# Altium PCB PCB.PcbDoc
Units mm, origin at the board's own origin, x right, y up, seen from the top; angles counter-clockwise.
Board outline 41 x 25.36 mm, 2 copper layers (TOP, BOTTOM), stack 1.586 mm thick; 59 components, 45 nets, 178 pads, 69 vias.
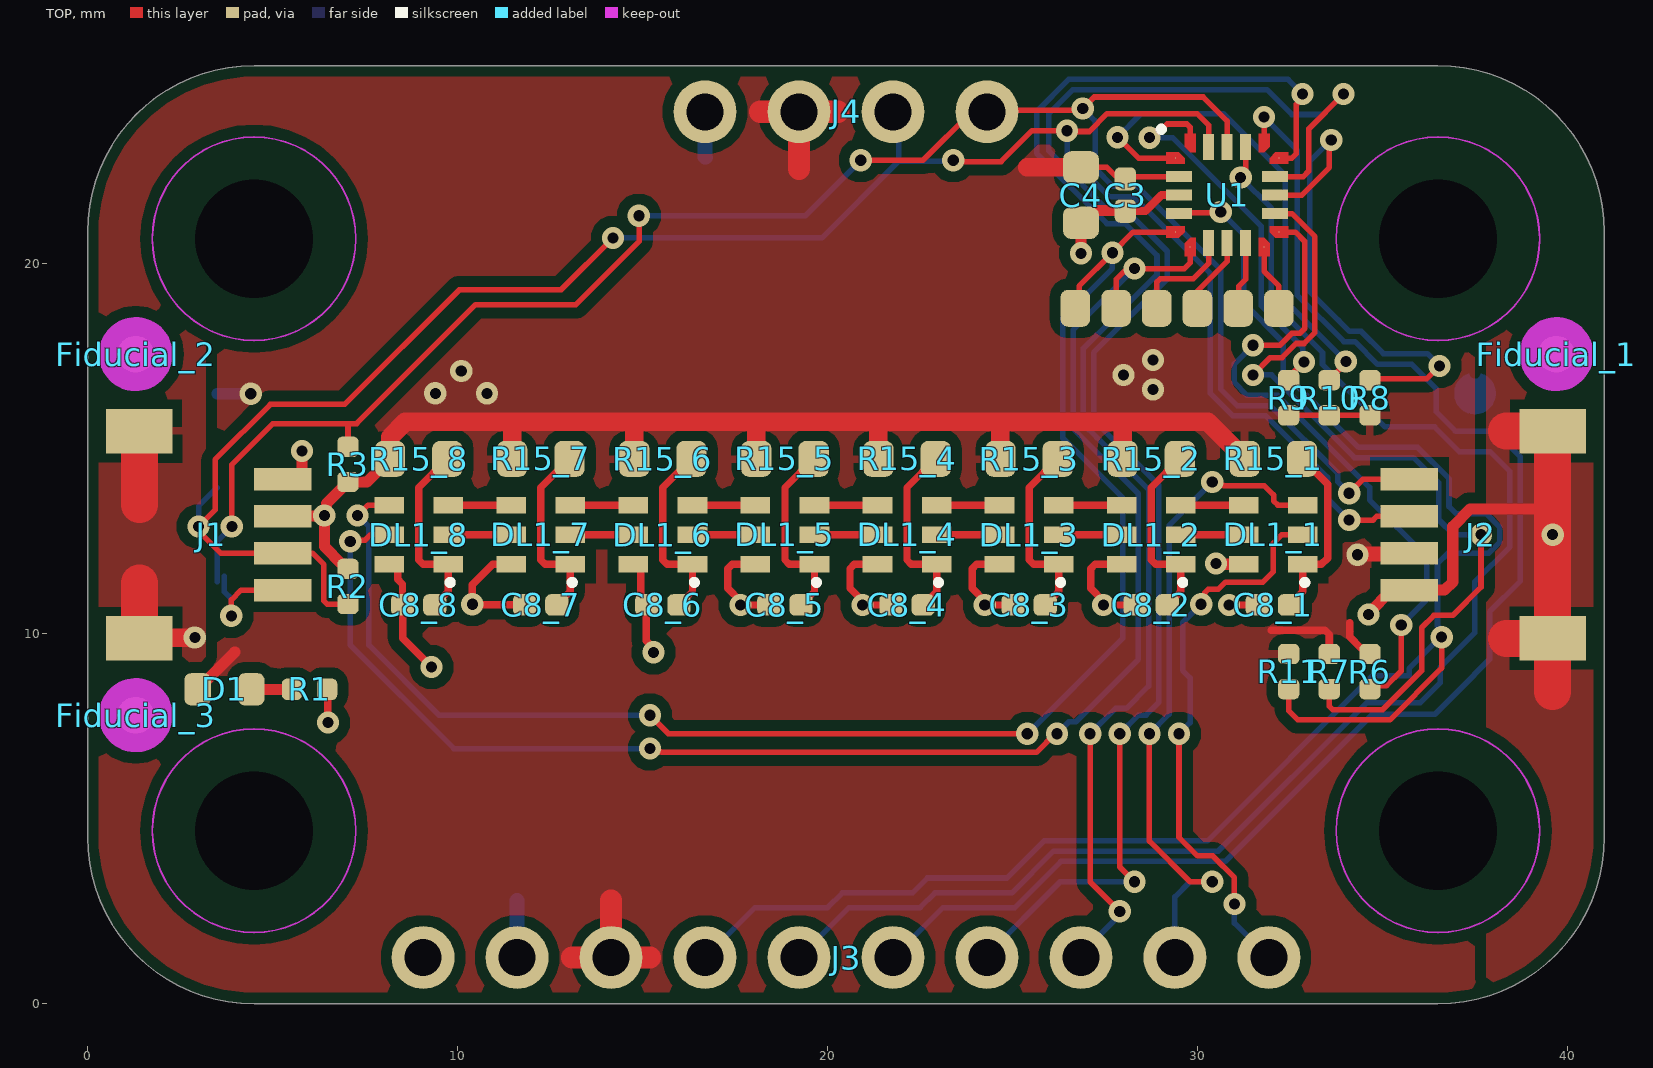
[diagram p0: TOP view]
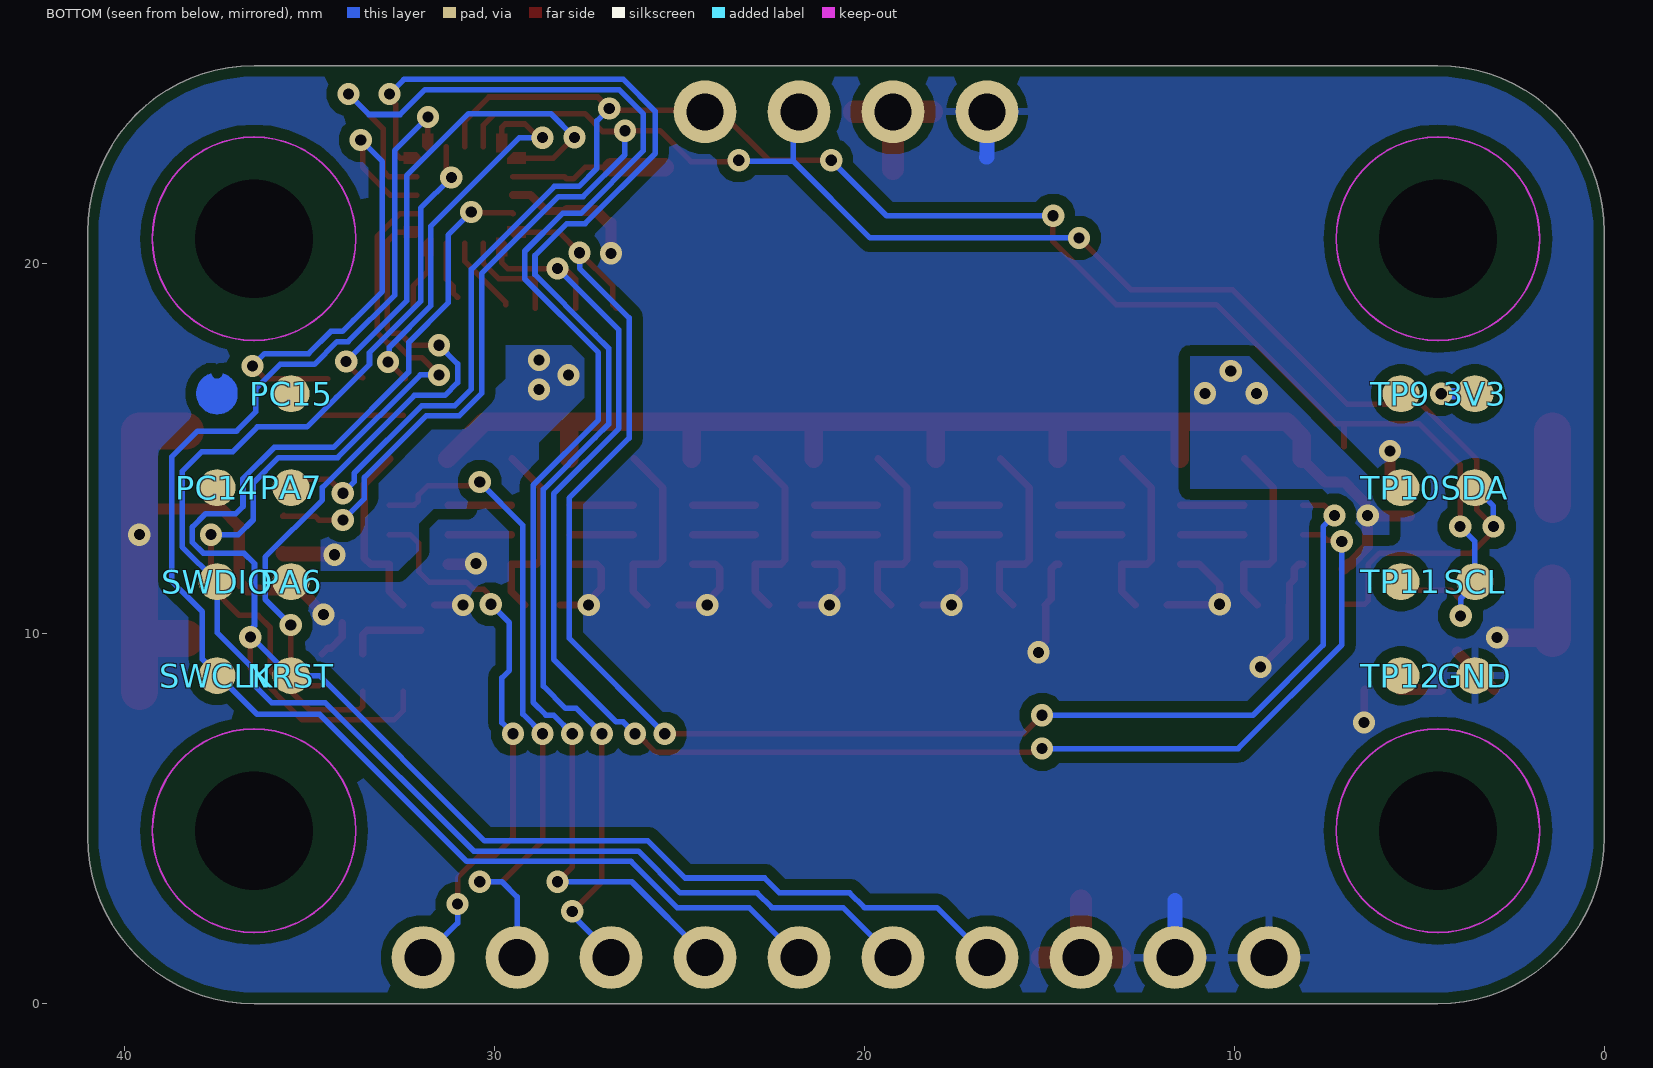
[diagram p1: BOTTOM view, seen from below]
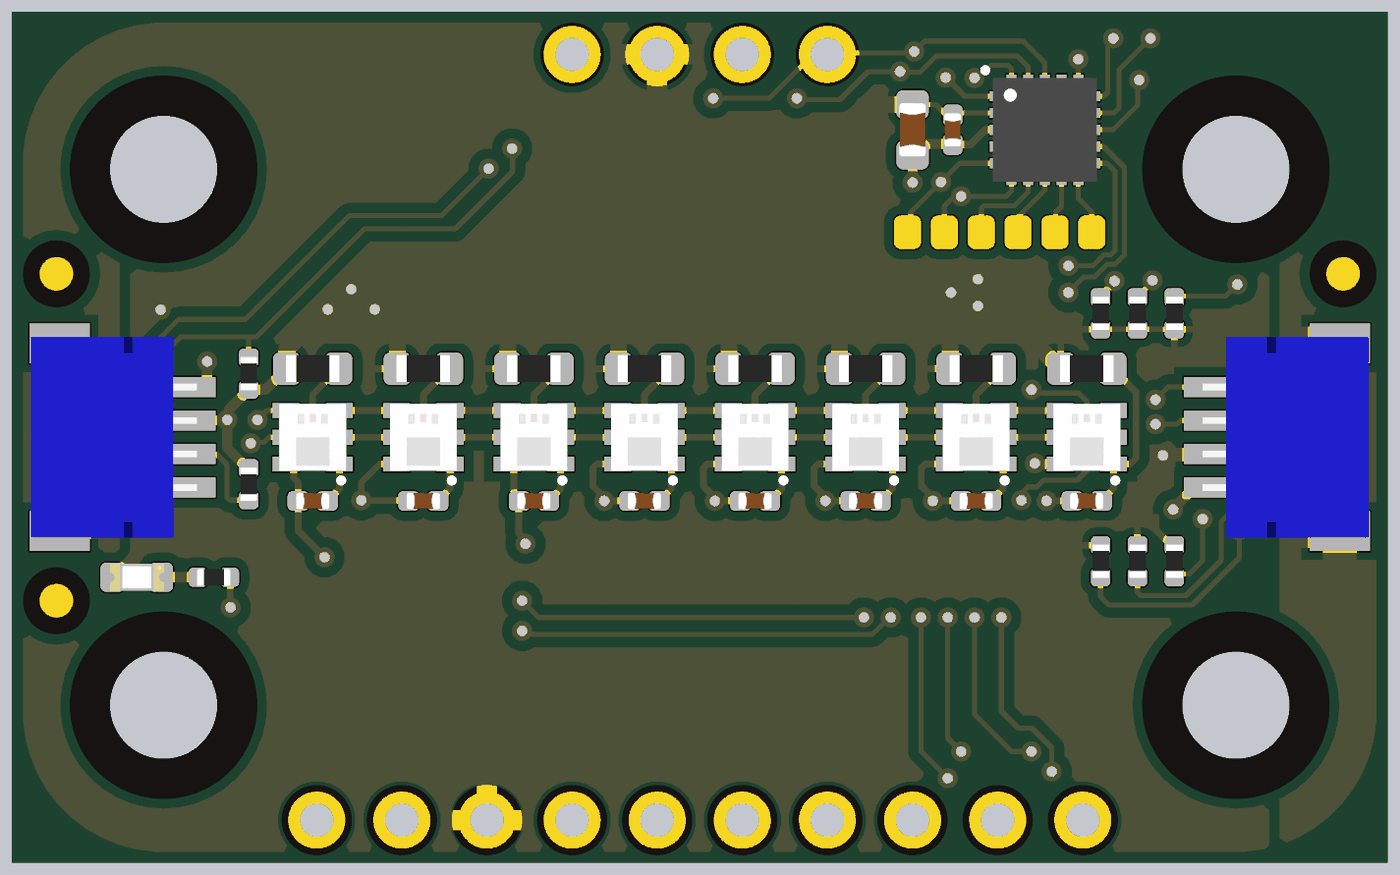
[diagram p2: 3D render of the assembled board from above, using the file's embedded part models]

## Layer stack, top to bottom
Top Solder: solder mask 0.01, Solder Resist, Dk 3.5
TOP: signal copper 0.018
Dielectric: core 1.55, FR-4, Dk 4.8
BOTTOM: signal copper 0.018
Bottom Solder: solder mask 0.01, Solder Resist, Dk 3.5

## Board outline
0,4.5 ccw(c4.5,4.5) 4.5,0 36.5,0 ccw(c36.5,4.5) 41,4.5 41,20.86 ccw(c36.5,20.86) 36.5,25.36 4.5,25.36 ccw(c4.5,20.86) 0,20.86

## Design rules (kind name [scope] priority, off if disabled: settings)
BoardOutlineClearance Mousebites [(ObjectKind = 'Pad') And (Name = 'Free-MOUSEBITE')] p1: gap=0 ignorepadtopadclearanceinfootprint=FALSE
BoardOutlineClearance Silks [(OnLayer('Top Overlay') OR OnLayer('Bottom Overlay'))] p2: gap=0 ignorepadtopadclearanceinfootprint=FALSE
BoardOutlineClearance [All] p3: gap=0.3 ignorepadtopadclearanceinfootprint=FALSE
Clearance COPPER_0.3mm [All] p1: gap=0.127 ignorepadtopadclearanceinfootprint=FALSE except(0.3: Arc-Fill Arc-Poly Arc-Region Track-Fill Track-Poly Track-Region SMDPad-Fill SMDPad-Poly SMDPad-Region THPad-Fill THPad-Poly THPad-Region Via-Fill Via-Poly Via-Region Fill-Fill Fill-Poly Fill-Region Poly-Poly Poly-Region Region-Region)
Clearance "Generic clearance 0.15mm" [All] p2: gap=0.15 ignorepadtopadclearanceinfootprint=TRUE
ComponentClearance [All] p1: gap=0.2 collisioncheckmode=3 verticalgap=0 showdistances=TRUE
DiffPairsRouting USB [InDifferentialPairClass('USB')] p1: maxlimit=0.15 minlimit=0.15 mostfreqgap=0.15 toplayer_minwidth=0.15 toplayer_maxwidth=0.21 toplayer_prefwidth=0.2 bottomlayer_minwidth=0.15 bottomlayer_maxwidth=0.21 bottomlayer_prefwidth=0.2 impedanceprofiledriven=TRUE impedanceprofileid={E6B00C31-4C8E-439C-824F-D2B2CDC26F9C} impedanceprofilevalue=90.000000 maxuncoupledlength=12.7
Height [All] p1: minheight=0 maxheight=30 prefheight=12.7
HoleSize [All] p1: absolutevalues=TRUE maxlimit=30 minlimit=0.3 maxpercent=80.000 minpercent=20.000
HoleToHoleClearance [All] p1: gap=0.25 allowstackedmicrovias=FALSE
MinimumAnnularRing [All] p1: minimumring=0.15
NetAntennae NetAntennae_2 [(ObjectKind = 'Track') And (Layer = 'TOP') And (Net = 'BOOST_INPUT') And (PropagationDelay = '4.136ps')] p1: netantennaetolerance=5
NetAntennae NetAntennae_1 [(ObjectKind = 'Track') And (Layer = 'TOP') And (Net = '+5V') And (PropagationDelay = '4.136ps')] p2: netantennaetolerance=5
NetAntennae [All] p3: netantennaetolerance=0
PlaneConnect [All] p1: pad.planeconnectstyle=Relief pad.reliefexpansion=0.508 pad.reliefentries=4 pad.reliefconductorwidth=0.254 pad.reliefairgap=0.254 via.planeconnectstyle=Direct via.reliefexpansion=0.508 via.reliefentries=4 via.reliefconductorwidth=0.254 via.reliefairgap=0.254
PolygonConnect [All] p1: thpad.connectstyle=Relief thpad.reliefconductorwidth=0.2 thpad.reliefentries=4 thpad.polygonreliefangle="90 Angle" thpad.airgapwidth=0.254 smdpad.connectstyle=Relief smdpad.reliefconductorwidth=0.2 smdpad.reliefentries=4 smdpad.polygonreliefangle="90 Angle" smdpad.airgapwidth=0.254 via.connectstyle=Direct via.reliefconductorwidth=0.254 via.reliefentries=4 via.polygonreliefangle="90 Angle" via.airgapwidth=0.254
RoomDefinition U_RGBLED2 [InComponentClass('U_RGBLED2')] p1: confinementstyle=ConfineIn formatcopy=TRUE lockcomponents=FALSE outline 30.325,14.055 30.325,11.04 29.875,11.04 29.875,10.115 27.625,10.115 27.625,11.04 27.175,11.04 27.175,14.055 27.19,14.055 27.19,15.59 30.31,15.59 30.31,14.055
RoomDefinition U_RGBLED3 [InComponentClass('U_RGBLED3')] p2: confinementstyle=ConfineIn formatcopy=TRUE lockcomponents=FALSE outline 27.025,14.055 27.025,11.04 26.575,11.04 26.575,10.115 24.325,10.115 24.325,11.04 23.875,11.04 23.875,14.055 23.89,14.055 23.89,15.59 27.01,15.59 27.01,14.055
RoomDefinition U_RGBLED1 [InComponentClass('U_RGBLED1')] p3: confinementstyle=ConfineIn formatcopy=TRUE lockcomponents=FALSE outline 33.525,14.055 33.525,11.04 33.075,11.04 33.075,10.115 30.825,10.115 30.825,11.04 30.375,11.04 30.375,14.055 30.39,14.055 30.39,15.59 33.51,15.59 33.51,14.055
RoomDefinition U_RGBLED4 [InComponentClass('U_RGBLED4')] p4: confinementstyle=ConfineIn formatcopy=TRUE lockcomponents=FALSE outline 23.725,14.055 23.725,11.04 23.275,11.04 23.275,10.115 21.025,10.115 21.025,11.04 20.575,11.04 20.575,14.055 20.59,14.055 20.59,15.59 23.71,15.59 23.71,14.055
RoomDefinition U_RGBLED5 [InComponentClass('U_RGBLED5')] p5: confinementstyle=ConfineIn formatcopy=TRUE lockcomponents=FALSE outline 20.525,14.055 20.525,11.04 20.075,11.04 20.075,10.115 17.825,10.115 17.825,11.04 17.375,11.04 17.375,14.055 17.39,14.055 17.39,15.59 20.51,15.59 20.51,14.055
RoomDefinition U_RGBLED6 [InComponentClass('U_RGBLED6')] p6: confinementstyle=ConfineIn formatcopy=TRUE lockcomponents=FALSE outline 17.125,14.055 17.125,11.04 16.675,11.04 16.675,10.115 14.425,10.115 14.425,11.04 13.975,11.04 13.975,14.055 13.99,14.055 13.99,15.59 17.11,15.59 17.11,14.055
RoomDefinition U_RGBLED7 [InComponentClass('U_RGBLED7')] p7: confinementstyle=ConfineIn formatcopy=TRUE lockcomponents=FALSE outline 27.175,11.305 27.175,14.32 27.625,14.32 27.625,15.245 29.875,15.245 29.875,14.32 30.325,14.32 30.325,11.305 30.31,11.305 30.31,9.77 27.19,9.77 27.19,11.305
RoomDefinition U_RGBLED8 [InComponentClass('U_RGBLED8')] p8: confinementstyle=ConfineIn formatcopy=TRUE lockcomponents=FALSE outline 10.525,14.055 10.525,11.04 10.075,11.04 10.075,10.115 7.825,10.115 7.825,11.04 7.375,11.04 7.375,14.055 7.39,14.055 7.39,15.59 10.51,15.59 10.51,14.055
RoomDefinition TOP [InComponentClass('TOP')] p9: confinementstyle=ConfineIn formatcopy=TRUE lockcomponents=FALSE outline 42.7,5.4 51.6,5.4 51.6,19.2 42.7,19.2
RoutingVias StandardVias [All] p1: holewidth=0.3 width=0.6 viastyle="Through Hole" minholewidth=0.3 minwidth=0.6 maxholewidth=0.3 maxwidth=0.6
SMDToCorner [All] p1: distance=39370
ShortCircuit ShortCircuit_2 [(ObjectKind = 'Pad') And (Component = 'SJ1') And (Name = 'SJ1-1')] p1: allowed=TRUE
ShortCircuit ShortCircuit_1 [(ObjectKind = 'Pad') And (Component = 'SJ2') And (Name = 'SJ2-2')] p2: allowed=TRUE
ShortCircuit [All] p3: allowed=FALSE
SilkToSilkClearance [All] p1: silktosilkclearance=0.2
SilkToSolderMaskClearance [IsPad] p1: minsilkscreentomaskgap=0.15 clearancetoexposedcopper=TRUE
SolderMaskExpansion VIAtented [IsVia] p1: expansion=0.102 istentingtop=TRUE
SolderMaskExpansion [All] p2: expansion=0.05 istentingtop=FALSE
UnConnectedPin [All] p1:
UnRoutedNet [not WithinRoom('K36')] p1: checkbadconnections=TRUE
ViasUnderSMD [All] p1: allowed=FALSE
Width StandardTraces [All] p1: maxlimit=5 minlimit=0.15 preferedwidth=0.15 minimp=50.000000 maximp=50.000000 favimp=50.000000
19 further rules are at their usual default settings.

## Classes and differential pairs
channel class RGBLED: U_RGBLED1 U_RGBLED2 U_RGBLED3 U_RGBLED4 U_RGBLED5 U_RGBLED6 U_RGBLED7 U_RGBLED8
component class U_RGBLED8: C8_8 DL1_8 R15_8
component class U_RGBLED7: C8_7 DL1_7 R15_7
component class U_RGBLED6: C8_6 DL1_6 R15_6
component class U_RGBLED5: C8_5 DL1_5 R15_5
component class U_RGBLED4: C8_4 DL1_4 R15_4
component class U_RGBLED3: C8_3 DL1_3 R15_3
component class U_RGBLED2: C8_2 DL1_2 R15_2
component class U_RGBLED1: C8_1 DL1_1 R15_1
component class TOP: 3V3 D1 Fiducial_1 Fiducial_2 Fiducial_3 GND J1 J2 J3 J4 NRST PA6 PA7 PC14 PC15 R1 SCL SDA SWCLK SWDIO TP9 TP10 TP11 TP12
component class U_MICROCONTROLLER: C3 C4 R2 R3 R6 R7 R8 R9 R10 R11 U1

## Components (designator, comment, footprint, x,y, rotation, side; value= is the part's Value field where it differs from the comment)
3V3 "Test point 1.00mm" TP-1.00MM 3.5,16.49 r90 bottom
C3 "0402B104K160CT" CAP-0402 28.05,21.86 r270 top value=100nF
C4 "GRM188R61C475KAAJD" CAP-0603 26.85,21.86 r90 top value=4.7µF
C8_1 "0402B104K160CT" CAP-0402 32.05,10.78 r180 top value=100nF (schematic designator C8)
C8_2 "0402B104K160CT" CAP-0402 28.75,10.78 r180 top value=100nF (schematic designator C8)
C8_3 "0402B104K160CT" CAP-0402 25.45,10.78 r180 top value=100nF (schematic designator C8)
C8_4 "0402B104K160CT" CAP-0402 22.15,10.78 r180 top value=100nF (schematic designator C8)
C8_5 "0402B104K160CT" CAP-0402 18.85,10.78 r180 top value=100nF (schematic designator C8)
C8_6 "0402B104K160CT" CAP-0402 15.55,10.78 r180 top value=100nF (schematic designator C8)
C8_7 "0402B104K160CT" CAP-0402 12.25,10.78 r180 top value=100nF (schematic designator C8)
C8_8 "0402B104K160CT" CAP-0402 8.95,10.78 r180 top value=100nF (schematic designator C8)
D1 "HSMG-C190" LEDC1608X80N-AK 3.7,8.5 r180 top
DL1_1 "LC8822-2020" APA102-2020 32.05,12.68 r180 top (schematic designator DL1)
DL1_2 "LC8822-2020" APA102-2020 28.75,12.68 r180 top (schematic designator DL1)
DL1_3 "LC8822-2020" APA102-2020 25.45,12.68 r180 top (schematic designator DL1)
DL1_4 "LC8822-2020" APA102-2020 22.15,12.68 r180 top (schematic designator DL1)
DL1_5 "LC8822-2020" APA102-2020 18.85,12.68 r180 top (schematic designator DL1)
DL1_6 "LC8822-2020" APA102-2020 15.55,12.68 r180 top (schematic designator DL1)
DL1_7 "LC8822-2020" APA102-2020 12.25,12.68 r180 top (schematic designator DL1)
DL1_8 "LC8822-2020" APA102-2020 8.95,12.68 r180 top (schematic designator DL1)
Fiducial_1 "Fiducial mark 1mm" "Fiducial mark 1mm-Footprint-1" 39.7,17.56 r270 top
Fiducial_2 "Fiducial mark 1mm" "Fiducial mark 1mm-Footprint-1" 1.3,17.56 r270 top
Fiducial_3 "Fiducial mark 1mm" "Fiducial mark 1mm-Footprint-1" 1.3,7.8 r270 top
GND "Test point 1.00mm" TP-1.00MM 3.5,8.87 r90 bottom
J1 "SM04B-SRSS-TB(LF)(SN)" SM04B-SRSS-TB(LF)(SN)-Footprint-1 3.337,12.68 r90 top locked
J2 "SM04B-SRSS-TB(LF)(SN)" SM04B-SRSS-TB(LF)(SN)-Footprint-1 37.663,12.68 r270 top locked
J3 "HEADER TH 2.54mm VERT. 1x010POS" "PIN HEADER 2.54mm VERT. 1x10POS" 20.5,1.25 r0 top
J4 "HEADER TH 2.54mm VERT. 1x004POS" "PIN HEADER 2.54mm VERT. 1x4POS-Footprint-1" 20.5,24.11 r0 top
NRST "Test point 1.00mm" TP-1.00MM 35.5,8.87 r180 bottom
PA6 "Test point 1.00mm" TP-1.00MM 35.5,11.41 r180 bottom
PA7 "Test point 1.00mm" TP-1.00MM 35.5,13.95 r180 bottom
PC14 "Test point 1.00mm" TP-1.00MM 37.5,13.95 r180 bottom
PC15 "Test point 1.00mm" TP-1.00MM 35.5,16.49 r180 bottom
R1 "CRCW04021K00FKEDC" RES-0402 6,8.5 r180 top value=1k
R2 "RC0402FR-074K7L" RES-0402 7.039,11.28 r90 top value=4.7k
R3 "RC0402FR-074K7L" RES-0402 7.039,14.58 r270 top value=4.7k
R6 "RC0402FR-074K7L" RES-0402 34.663,8.98 r270 top value=4.7k
R7 "RC0402FR-074K7L" RES-0402 33.563,8.98 r270 top value=4.7k
R8 "RC0402FR-074K7L" RES-0402 34.663,16.38 r90 top value=4.7k
R9 "RC0402FR-074K7L" RES-0402 32.463,16.38 r90 top value=4.7k
R10 "RC0402FR-074K7L" RES-0402 33.563,16.38 r90 top value=4.7k
R11 "RC0402FR-074K7L" RES-0402 32.463,8.98 r270 top value=4.7k
R15_1 "CRCW060310R0FKEAC" RES-0603 32.05,14.73 r180 top value=10 (schematic designator R15)
R15_2 "CRCW060310R0FKEAC" RES-0603 28.75,14.73 r180 top value=10 (schematic designator R15)
R15_3 "CRCW060310R0FKEAC" RES-0603 25.45,14.73 r180 top value=10 (schematic designator R15)
R15_4 "CRCW060310R0FKEAC" RES-0603 22.15,14.73 r180 top value=10 (schematic designator R15)
R15_5 "CRCW060310R0FKEAC" RES-0603 18.85,14.73 r180 top value=10 (schematic designator R15)
R15_6 "CRCW060310R0FKEAC" RES-0603 15.55,14.73 r180 top value=10 (schematic designator R15)
R15_7 "CRCW060310R0FKEAC" RES-0603 12.25,14.73 r180 top value=10 (schematic designator R15)
R15_8 "CRCW060310R0FKEAC" RES-0603 8.95,14.73 r180 top value=10 (schematic designator R15)
SCL "Test point 1.00mm" TP-1.00MM 3.5,11.41 r90 bottom
SDA "Test point 1.00mm" TP-1.00MM 3.5,13.95 r90 bottom
SWCLK "Test point 1.00mm" TP-1.00MM 37.5,8.87 r180 bottom
SWDIO "Test point 1.00mm" TP-1.00MM 37.5,11.41 r180 bottom
TP9 "Test point 1.00mm" TP-1.00MM 5.5,16.49 r0 bottom
TP10 "Test point 1.00mm" TP-1.00MM 5.5,13.95 r0 bottom
TP11 "Test point 1.00mm" TP-1.00MM 5.5,11.41 r0 bottom
TP12 "Test point 1.00mm" TP-1.00MM 5.5,8.87 r0 bottom
U1 "STM32C011F4U6TR" UFQFPN20 30.8,21.86 r0 top

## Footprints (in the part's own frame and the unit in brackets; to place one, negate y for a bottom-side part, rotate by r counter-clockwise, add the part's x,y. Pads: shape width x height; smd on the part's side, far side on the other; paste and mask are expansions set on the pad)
APA102-2020 [mm]
  rect 0.8x0.45 smd mask+0.05: 1(-0.8,0.8) 2(-0.8,0) 3(-0.8,-0.8) 4(0.8,0.8) 5(0.8,0) 6(0.8,-0.8)
  silkscreen extent -0.9,1.24 -0.8,1.34, body extent -1,-1 1,1, height 0.92
CAP-0402 [mm] "Chip Capacitor, 2-Leads, Body  0402 (in) 1005 (mm), IPC Medium Density"
  rrect52% 0.63x0.58 smd mask+0.05: 1(-0.435,0) 2(0.435,0)
  body extent -0.5,-0.25 0.5,0.25, height 0.5
CAP-0603 [mm] "Chip Capacitor, Body 0603 imperial,1.6x0.8mm, IPC High Density"
  rrect51% 0.87x0.97 smd mask+0.05: 1(-0.75,0) 2(0.75,0)
  body extent -0.8,-0.4 0.8,0.4, height 0.8
"Fiducial mark 1mm-Footprint-1" [mm]
  round 1 smd paste-10 mask+0.5: 1(0,0)
  TOP keep-out circle w1: c0,0 r0.5
LEDC1608X80N-AK [mm]
  rrect50% 0.72x0.87 smd: A(0.725,0) C(-0.725,0)
  body extent -0.8,-0.4 0.8,0.4, height 0.79
"PIN HEADER 2.54mm VERT. 1x4POS-Footprint-1" [mm]
  round 1.7 hole 1 mask+0.1: 1(-3.81,0) 2(-1.27,0) 3(1.27,0) 4(3.81,0)
"PIN HEADER 2.54mm VERT. 1x10POS" [mm]
  round 1.7 hole 1 mask+0.2: 1(-11.43,0) 2(-8.89,0) 3(-6.35,0) 4(-3.81,0) 5(-1.27,0) 6(1.27,0) 7(3.81,0) 8(6.35,0) 9(8.89,0) 10(11.43,0)
RES-0402 [mm] "Chip Resistor, 2-Leads, Body  0402 (in) 1005 (mm), IPC Medium Density"
  rrect51% 0.55x0.58 smd mask+0.05: 1(-0.475,0) 2(0.475,0)
  body extent -0.5,-0.25 0.5,0.25, height 0.34
RES-0603 [mm] "Chip Resistor - Body 0603 imperial,1.6x0.8mm, IPC High Density"
  rrect51% 0.82x0.97 smd mask+0.05: 1(-0.775,0) 2(0.775,0)
  body extent -0.8,-0.4 0.8,0.4, height 0.43
SM04B-SRSS-TB(LF)(SN)-Footprint-1 [mm]
  rect 0.6x1.55 smd mask+0.05: 1(1.5,-1.937) 2(0.5,-1.937) 3(-0.5,-1.937) 4(-1.5,-1.937)
  rect 1.2x1.8 smd mask+0.05: FIX(-2.8,1.938) FIX(2.8,1.938)
  body extent -3,-2.16 3,2.8, height 2.98
TP-1.00MM [mm]
  rrect100% 1x1 smd paste-2.54: X(0,0)
UFQFPN20 [mm] "QFN, 20-Leads, Body 3.00x3.00mm, Pitch 0.50mm, IPC Medium Density"
  round 0.025 smd mask+0.05: 1(-1.4,1) 5(-1.4,-1) 6(-1,-1.4) 10(1,-1.4) 11(1.4,-1) 15(1.4,1) 16(1,1.4) 20(-1,1.4)
  rect 0.7x0.3 smd mask+0.05: 2(-1.3,0.5) 3(-1.3,0) 4(-1.3,-0.5) 12(1.3,-0.5) 13(1.3,0) 14(1.3,0.5)
  rect 0.3x0.7 smd mask+0.05: 7(-0.5,-1.3) 8(0,-1.3) 9(0.5,-1.3) 17(0.5,1.3) 18(0,1.3) 19(-0.5,1.3)
  TOP region: -1.3,-1.15 -1.15,-1 -1.15,-0.85 -1.65,-0.85 -1.65,-1.15
  TOP region: -0.85,-1.65 -1.15,-1.65 -1.15,-1.3 -1,-1.15 -0.85,-1.15
  TOP region: 1.15,-1.65 0.85,-1.65 0.85,-1.15 1,-1.15 1.15,-1.3
  TOP region: 1.65,1.15 1.65,0.85 1.15,0.85 1.15,1 1.3,1.15
  TOP region: 1,1.15 0.85,1.15 0.85,1.65 1.15,1.65 1.15,1.3
  TOP region: -1.15,1 -1.15,0.85 -1.65,0.85 -1.65,1.15 -1.3,1.15
  TOP region: -1.15,1.3 -1,1.15 -0.85,1.15 -0.85,1.65 -1.15,1.65
  TOP region: 1.65,-0.85 1.65,-1.15 1.3,-1.15 1.15,-1 1.15,-0.85
  silkscreen extent -1.8,1.75 -1.75,1.8, body extent -1.55,-1.55 1.55,1.55, height 0.6

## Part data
3V3 GND NRST PA6 PA7 PC14 PC15 SCL SDA SWCLK SWDIO TP9 TP10 TP11 TP12: library part UT0013-A.6, Manufacturer="This is not a component"
C3 C8_1 C8_2 C8_3 C8_4 C8_5 C8_6 C8_7 C8_8: library part C0012-A.15, "CAP CHIP 0402 100nF 10% 16V X7R", Case Code (Imperial)=0402, Dielectric=X7R, Manufacturer=Walsin, Tolerance=10%, Voltage=16V
C4: library part C0054-A.16, "CAP CHIP 0603 4.7uF 10% 16V X5R", Case Code (Imperial)=0603, Dielectric=X5R, Manufacturer=Murata, Manufacturer 3="Samsung Electro-Mechanics", Part number 2=GRM188R61C475KE11D, Part number 3=CL10A475KO8NNNC, Tolerance=10%, Voltage=16V
D1: library part L0009-A.5, "LED SMD 0603 GREEN/568 15mcd 120^", Manufacturer=Broadcom
DL1_1 DL1_2 DL1_3 DL1_4 DL1_5 DL1_6 DL1_7 DL1_8: library part L0003-A.11, "LED RGB DATA + CLOCK 2020 2x2x.0.7mm", Manufacturer="Shenzhen LED Color Opto Electronic CO.,LTD."
Fiducial_1 Fiducial_2 Fiducial_3: library part UT0023-A.7, "Fiducial mark 1mm clearance 2mm"
J1 J2: library part J0005-A.2, "CONN JST 4POS SIDE 1MM TIN QWIIC", Manufacturer=JST
J3: library part J0169-A.8
J4: library part J0162-A.5
R1: library part R0007-A.24, "RES CHIP 0402 1k 1% 1/16W", Case Code (Imperial)=0402, Manufacturer=Vishay, Power=62.5mW, Temperature Coefficient=100ppm, Tolerance=1%
R2 R3 R6 R7 R8 R9 R10 R11: library part R0013-A.24, "RES CHIP 0402 4k7 1% 1/16W", Case Code (Imperial)=0402, Manufacturer=YAGEO, Power=62.5mW, Temperature Coefficient=200ppm, Tolerance=1%
R15_1 R15_2 R15_3 R15_4 R15_5 R15_6 R15_7 R15_8: library part R0188-A.20, "RES CHIP 0603 10R 1% 1/10W", Case Code (Imperial)=0603, Manufacturer=Vishay, Power=100mW, Temperature Coefficient=100ppm, Tolerance=1%
U1: library part U0363-A.3, "IC Cortex M0, 32b MCU, 32KB Flash, 6KB RAM, VDD 2-3.6V, -40°C to 85°C, QFN20 3x3mm", Manufacturer="ST Microelectronics"

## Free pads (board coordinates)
  rrect50% 0.8x1 smd paste-2539.97: 3V8(28.9,18.8) 3V9(26.7,18.8) 3V9(27.8,18.8) 3V9(30,18.8) 3V10(31.1,18.8) 3V10(32.2,18.8)
  round 3 hole 3.2 unplated paste-2539.97 mask+1.3: MH(4.5,4.68) MH(4.5,20.68) MH(36.5,4.68) MH(36.5,20.68)

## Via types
v1: diameter 0.6, hole 0.3, TOP to BOTTOM, tented both sides, 69 vias

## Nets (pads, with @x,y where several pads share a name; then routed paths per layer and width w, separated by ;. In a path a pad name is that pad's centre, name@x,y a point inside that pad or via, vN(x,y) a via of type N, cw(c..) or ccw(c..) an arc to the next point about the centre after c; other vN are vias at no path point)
+3V3: 3V3.X C3.1 C4.2 D1.A J1.2 J2.2 J3.3 J4.2 R2.2 R3.2 R6.1 R7.1 R8.1 R9.1 R10.1 R11.1 R15_1.2 R15_2.2 R15_3.2 R15_4.2 R15_5.2 R15_6.2 R15_7.2 R15_8.2 U1.2 | length 56.7
  TOP w0.15: C4.2 27.55,22.61 27.865,22.295 C3.1 28.115,22.36 U1.2 ; R9.1 R10.1 R8.1
  TOP w0.2: 31.998,10.1 33.446,10.1 33.563,9.983 R7.1 ; 34.113,10.298 34.113,9.916 34.424,9.605 34.513,9.605 R6.1
  TOP w0.3: D1.A 3.98,9.505 ; J1.2 5.284,13.19 6.39,13.19 v1(6.4,13.2) ; R2.2 6.914,11.88 6.877,11.88 6.4,12.357 v1(6.4,13.2) ; R15_8.2 7.55,14.105 R3.2 7.024,14.105 6.899,13.98 6.899,13.965 6.457,13.523 6.457,13.257 v1(6.4,13.2)
  TOP w0.4: v1(34.324,12.138) 34.344,12.159 35.705,12.159 J2.2
  TOP w0.5: R15_8.2 8.175,15.315 8.59,15.73 30.275,15.73 R15_1.2 ; R15_7.2 11.475,15.73 ; R15_6.2 14.775,15.73 ; R15_5.2 18.075,15.73 ; R15_4.2 21.375,15.73 ; R15_3.2 24.675,15.73 ; 25.4,22.61 C4.2 ; R15_2.2 27.975,15.73
  TOP w0.6: 13.1,1.25 J3.3 ; 14.15,2.79 J3.3 ; 15.2,1.25 J3.3 ; 18.18,24.11 J4.2 ; 19.23,22.57 J4.2 ; 20.28,24.11 J4.2
  BOTTOM w0.15: J3.3 J3.3@14.37,1.25
  BOTTOM w0.3: 3V3.X v1(4.41,16.49)
  other v1: 9.4,16.5 10.8,16.5 28.8,16.6 28,17 10.1,17.1 28.8,17.4
CO_1: DL1_1.2 J3.10 | length 15.3
  TOP w0.15: v1(29.5,7.3) 29.5,4.5 30.002,3.998 30.412,3.998 31,3.41 v1(31,2.7) ; v1(30.1,10.8) 30.1,10.922 30.2,11.022 30.2,11.112 30.288,11.2 30.56,11.2 30.76,11.4 31.77,11.4 32.05,11.68 32.05,12.45 32.28,12.68 DL1_1.2
  BOTTOM w0.15: v1(29.5,7.3) 29.8,7.6 29.8,8.811 29.6,9.011 29.6,10.3 v1(30.1,10.8) ; v1(31,2.7) 31,2.18 J3.10
DO_1: DL1_1.3 J3.9 | length 18.2
  TOP w0.15: v1(28.7,7.3) 28.7,4.4 29.8,3.3 v1(30.4,3.3) ; v1(30.4,14.1) 30.486,14.014 30.699,14.014 30.713,14 31.809,14 32.057,13.752 32.057,13.595 32.172,13.48 DL1_1.3
  BOTTOM w0.15: v1(28.7,7.3) 29.231,7.831 29.231,12.931 v1(30.4,14.1) ; J3.9 29.39,2.89 29.8,3.3 v1(30.4,3.3)
GND: C3.2 C4.1 C8_1.2 C8_2.2 C8_3.2 C8_4.2 C8_5.2 C8_6.2 C8_7.2 C8_8.2 DL1_1.4 DL1_2.4 DL1_3.4 DL1_4.4 DL1_5.4 DL1_6.4 DL1_7.4 DL1_8.4 GND.X J1.1 J1.FIX J2.1 J2.FIX J3.1 J3.2 J4.1 R1.1 U1.3 | length 51.8
  TOP w0.2: R1.1 6.488,8.488 6.488,7.612 v1(6.5,7.6) ; DL1_8.4 8.258,11.88 8.383,11.755 8.383,11.472 8.513,11.342 C8_8.2@8.513,10.78 ; C8_8.2 8.515,9.885 v1(9.3,9.1) ; DL1_7.4 10.95,11.88 10.4,11.33 v1(10.4,10.8) 10.41,10.79 11.805,10.79 C8_7.2 ; DL1_6.4 14.827,11.88 14.952,11.755 14.952,10.943 C8_6.2 ; C8_6.2@15.1,10.78 15.1,9.808 15.3,9.608 v1(15.3,9.5) ; DL1_5.4 17.426,11.88 17.309,11.763 17.309,11.229 17.65,10.888 v1(17.65,10.78) C8_5.2 ; DL1_4.4 20.726,11.88 20.609,11.763 20.609,11.229 20.95,10.888 v1(20.95,10.78) C8_4.2 ; DL1_3.4 24.026,11.88 23.909,11.763 23.909,11.229 24.25,10.888 v1(24.25,10.78) C8_3.2 ; DL1_2.4@27.855,11.88 27.231,11.88 27.114,11.763 27.114,11.229 27.455,10.888 v1(27.455,10.78) C8_2.2@28.22,10.78 ; v1@30.85,10.888 v1(30.85,10.78) C8_1.2
  TOP w0.22: C3.2 28.592,21.425 29.027,21.86 U1.3
  TOP w0.3: J1.1 5.648,14.18 5.798,14.33 v1(5.798,14.943) ; v1(26.854,20.284) v1(26.854,20.284) 26.852,21.108 C4.1 26.939,21.11 27.268,21.439 C3.2@28.036,21.439 ; v1(30.5,11.9) 30.52,11.88 DL1_1.4 ; v1(34.625,10.524) 34.625,10.555 35.251,11.18 J2.1 36.68,11.18 36.9,11.4 36.9,12.9 37.372,13.372 39.528,13.372 39.601,13.3
  TOP w0.5: J1.FIX@1.399,9.88 1.419,9.9 2.667,9.9 v1(2.9,9.9)
  TOP w1: J1.FIX@1.399,9.88 1.399,11.379 ; 1.399,13.499 J1.FIX@1.399,15.48 ; 38.353,9.88 J2.FIX@39.601,9.88 ; 38.353,15.48 39.601,15.48 39.601,13.3 J2.FIX@39.601,9.88 ; 39.601,8.443 J2.FIX@39.601,9.88
  BOTTOM w0.4: J3.2 11.61,2.79 ; J4.1 16.69,22.89 16.7,22.88
  other v1: 39.6,12.68
NetC8_1_1: C8_1.1 DL1_1.1 R15_1.1 | length 5
  TOP w0.2: C8_1.1 32.85,11.145 DL1_1.1 33.35,11.88 33.516,12.046 33.516,14.039 R15_1.1
NetC8_2_1: C8_2.1 DL1_2.1 R15_2.1 | length 5.2
  TOP w0.2: C8_2.1 29.55,11.145 DL1_2.1 28.867,11.88 28.75,11.997 28.75,13.955 R15_2.1
NetC8_3_1: C8_3.1 DL1_3.1 R15_3.1 | length 5.2
  TOP w0.2: C8_3.1 26.25,11.145 DL1_3.1 25.567,11.88 25.45,11.997 25.45,13.955 R15_3.1
NetC8_4_1: C8_4.1 DL1_4.1 R15_4.1 | length 5.2
  TOP w0.2: C8_4.1 22.95,11.145 DL1_4.1 22.267,11.88 22.15,11.997 22.15,13.955 R15_4.1
NetC8_5_1: C8_5.1 DL1_5.1 R15_5.1 | length 5.2
  TOP w0.2: C8_5.1 19.65,11.145 DL1_5.1 18.967,11.88 18.85,11.997 18.85,13.955 R15_5.1
NetC8_6_1: C8_6.1 DL1_6.1 R15_6.1 | length 5.2
  TOP w0.2: C8_6.1 16.35,11.145 DL1_6.1 15.667,11.88 15.55,11.997 15.55,13.955 R15_6.1
NetC8_7_1: C8_7.1 DL1_7.1 R15_7.1 | length 5.2
  TOP w0.2: C8_7.1 13.05,11.145 DL1_7.1 12.367,11.88 12.25,11.997 12.25,13.955 R15_7.1
NetC8_8_1: C8_8.1 DL1_8.1 R15_8.1 | length 5.2
  TOP w0.2: C8_8.1 9.75,11.145 DL1_8.1 9.067,11.88 8.95,11.997 8.95,13.955 R15_8.1
NetD1_C: D1.C R1.2 | length 1.1
  TOP w0.3: D1.C R1.2
NetDL1_2_2: DL1_1.5 DL1_2.2 | length 1.7
  TOP w0.2: DL1_2.2 DL1_1.5
NetDL1_2_3: DL1_1.6 DL1_2.3 | length 1.7
  TOP w0.2: DL1_2.3 DL1_1.6
NetDL1_3_2: DL1_2.5 DL1_3.2 | length 1.7
  TOP w0.2: DL1_3.2 DL1_2.5
NetDL1_3_3: DL1_2.6 DL1_3.3 | length 1.7
  TOP w0.2: DL1_3.3 DL1_2.6
NetDL1_4_2: DL1_3.5 DL1_4.2 | length 1.7
  TOP w0.2: DL1_4.2 DL1_3.5
NetDL1_4_3: DL1_3.6 DL1_4.3 | length 1.7
  TOP w0.2: DL1_4.3 DL1_3.6
NetDL1_5_2: DL1_4.5 DL1_5.2 | length 1.7
  TOP w0.2: DL1_5.2 DL1_4.5
NetDL1_5_3: DL1_4.6 DL1_5.3 | length 1.7
  TOP w0.2: DL1_5.3 DL1_4.6
NetDL1_6_2: DL1_5.5 DL1_6.2 | length 1.7
  TOP w0.2: DL1_6.2 DL1_5.5
NetDL1_6_3: DL1_5.6 DL1_6.3 | length 1.7
  TOP w0.2: DL1_6.3 DL1_5.6
NetDL1_7_2: DL1_6.5 DL1_7.2 | length 1.7
  TOP w0.2: DL1_7.2 DL1_6.5
NetDL1_7_3: DL1_6.6 DL1_7.3 | length 1.7
  TOP w0.2: DL1_7.3 DL1_6.6
NetDL1_8_2: DL1_7.5 DL1_8.2 | length 1.7
  TOP w0.2: DL1_8.2@9.75,12.68 DL1_7.5
NetDL1_8_3: DL1_7.6 DL1_8.3 | length 1.7
  TOP w0.2: DL1_8.3@9.75,13.48 DL1_7.6
NetU1_7: pad.3V8 U1.7 | length 2.9
  TOP w0.15: pad.3V8 28.9,19.508 28.988,19.596 29.884,19.596 30.3,20.012 U1.7
NetU1_8: pad.3V9@30,18.8 U1.8 | length 2.1
  TOP w0.15: pad.3V9@29.7,18.9 29.7,18.968 30.8,20.068 U1.8
NetU1_9: pad.3V10@31.1,18.8 U1.9 | length 1.6
  TOP w0.15: pad.3V10@31,19.1 31.002,19.1 31.117,19.215 31.117,19.4 31.3,19.583 U1.9
NetU1_10: pad.3V10@32.2,18.8 U1.10 | length 1.8
  TOP w0.15: U1.10 31.8,19.8 32.2,19.4 pad.3V10@32.2,18.8
PA0_1: DL1_8.6 pad.3V9@26.7,18.8 U1.5 | length 42.5
  TOP w0.15: v1(7.3,13.2) 7.58,13.48 DL1_8.6 ; v1(15.2,7.8) 15.7,7.3 v1(25.4,7.3) ; pad.3V9@26.7,18.8 26.8,18.9 26.8,19.4 v1(27.7,20.3) 28.26,20.86 U1.5
  BOTTOM w0.15: v1(7.3,13.2) 7.602,12.898 7.602,9.698 9.5,7.8 v1(15.2,7.8) ; v1(25.4,7.3) 27.985,9.885 27.985,13.667 26.364,15.288 26.364,18.541 27.7,19.877 v1(27.7,20.3)
PA1_1: DL1_8.5 pad.3V9@27.8,18.8 U1.6 | length 42.8
  TOP w0.15: v1(7.1,12.5) 7.13,12.53 7.5,12.53 7.65,12.68 DL1_8.5 ; v1(15.2,6.9) 15.286,6.814 15.497,6.814 15.513,6.798 25.649,6.798 26.151,7.3 v1(26.2,7.3) ; pad.3V9@27.8,18.8 27.8,19.581 28.091,19.873 v1(28.3,19.873) 29.644,19.873 29.8,20.028 U1.6
  BOTTOM w0.15: v1(7.1,12.5) 7.1,9.7 9.9,6.9 v1(15.2,6.9) ; v1(26.2,7.3) 26.524,7.624 26.714,7.624 28.4,9.31 28.4,13.791 26.641,15.55 26.641,18.214 v1(28.3,19.873)
PA6_2: R6.2 U1.11 | length 17.8
  TOP w0.15: v1(31.5,17.8) 32.229,17.8 32.554,18.125 32.768,18.125 32.899,18.255 32.899,20.609 32.648,20.86 U1.11 ; R6.2@34.597,8.6 35.109,8.6 35.508,8.999 v1(35.508,10.241)
  BOTTOM w0.15: v1(31.5,17.8) 30.998,17.298 30.998,16.792 31.344,16.446 32.164,16.446 34.652,13.958 34.652,13.622 36.202,12.072 36.202,10.935 v1(35.508,10.241)
PA7_2: R7.2 U1.12 | length 22.6
  TOP w0.15: v1(31.5,17) 31.967,17.467 32.288,17.467 32.669,17.848 32.883,17.848 33.176,18.141 33.176,20.734 32.55,21.36 U1.12 ; R7.2@33.563,8.45 33.563,8.041 33.651,7.953 35.008,7.953 36.056,9.002 36.056,10.164 36.392,10.5 36.9,10.5 37.663,11.263 v1(37.663,12.68)
  BOTTOM w0.15: v1(31.5,17) 32.002,17 34.241,14.761 35.839,14.761 36.521,14.079 36.521,13.084 36.925,12.68 v1(37.663,12.68)
PA8_2: R8.2 U1.13 | length 13.4
  TOP w0.15: U1.13 32.822,21.86 33.567,22.605 33.567,23.3 v1(33.615,23.347) ; R8.2@34.514,16.9 36.2,16.9 v1(36.543,17.243)
  BOTTOM w0.15: v1(33.615,23.347) 33.029,22.762 33.029,19.258 33.816,18.471 34.114,18.173 34.427,18.173 35.027,17.573 36.212,17.573 v1(36.543,17.243)
PA9_USART1_TX_1: J3.7 U1.14 | length 41.7
  TOP w0.15: v1(27.9,7.3) 27.9,3.7 v1(28.3,3.3) ; U1.14 32.86,22.36 33.008,22.508 33.008,23.648 v1(33.95,24.59)
  BOTTOM w0.15: J3.7 24.31,1.32 26.29,3.3 v1(28.3,3.3) ; v1(27.9,7.3) 28.402,7.802 28.61,7.802 28.954,8.146 28.954,14.02 27.195,15.779 27.195,17.603 29.184,19.592 29.184,20.341 28.159,21.365 27.668,21.365 25.975,23.059 25.975,24.05 26.633,24.708 31.88,24.708 32.551,24.037 33.397,24.037 v1(33.95,24.59)
PA10_USART1_RX_1: J3.8 U1.15 | length 37.6
  TOP w0.15: v1(27.1,7.3) 27.1,3.3 v1(27.9,2.5) ; U1.15 32.554,22.86 32.671,22.977 32.671,24.312 32.841,24.482 v1(32.841,24.591)
  BOTTOM w0.15: J3.8 26.85,1.35 27.9,2.4 v1(27.9,2.5) ; v1(27.1,7.3) 27.787,7.987 28.077,7.987 28.677,8.587 28.677,13.906 27.28,15.303 26.918,15.665 26.918,17.718 27.28,18.08 28.907,19.707 28.907,20.226 28.045,21.088 27.554,21.088 25.655,22.987 25.655,24.122 26.518,24.985 32.446,24.985 v1(32.841,24.591)
PA13_SWDIO_1: J3.6 SWCLK.X U1.16 | length 39.5
  TOP w0.15: v1@31.744,24.019 v1(31.795,23.968) 31.8,23.963 U1.16
  BOTTOM w0.15: J3.6 23.12,2.6 25.062,2.6 26.312,3.849 30.751,3.849 34.724,7.823 36.413,7.823 37.48,8.89 37.48,8.899 37.9,9.319 37.9,10.6 38.719,11.419 38.719,14.791 38.029,15.481 36.974,15.481 36.456,16 36.456,16.62 35.794,17.282 34.869,17.282 34.255,17.896 33.955,17.896 32.702,19.149 32.702,23.061 v1(31.795,23.968)
PA14_SWCLK_BOOT0_1: J3.5 SWDIO.X U1.17 | length 40
  TOP w0.15: v1(31.167,22.336) 31.167,22.429 31.3,22.562 U1.17
  BOTTOM w0.15: J3.5 20.58,2.6 22.5,2.6 22.9,3 24.984,3 26.111,4.126 30.562,4.126 34.578,8.143 36.027,8.143 36.557,8.673 36.557,9.089 37.5,10.032 SWDIO.X 38.442,12.352 38.442,14.393 37.907,14.927 37.073,14.927 36.408,15.592 35.071,15.592 34.274,16.389 33.379,17.284 33.379,17.603 31.998,18.984 31.998,21.506 v1(31.167,22.336)
PC14_2: R9.2 U1.20 | length 10.5
  TOP w0.15: v1(28.7,23.41) 28.808,23.41 29.178,23.781 29.712,23.781 29.8,23.693 U1.20 ; R9.2@32.419,16.899 32.867,17.346 v1(32.877,17.346)
  BOTTOM w0.15: v1(28.7,23.41) 29.33,23.41 31.721,21.02 31.721,18.869 32.844,17.746 32.844,17.379 v1(32.877,17.346)
PC15_2: R10.2 U1.1 | length 13.6
  TOP w0.15: v1@27.85,23.42 28.41,22.86 U1.1 ; R10.2@33.563,16.918 33.575,16.93 33.618,16.93 34.009,17.321 v1(34.009,17.364)
  BOTTOM w0.15: v1(27.84,23.42) 28.48,24.06 30.698,24.06 32.375,22.383 32.375,18.998 v1(34.009,17.364)
PF2_N\R\S\T\_1: J3.4 NRST.X R11.2 U1.4 | length 48.3
  TOP w0.15: U1.4 29.52,21.38 30.61,21.38 v1(30.63,21.4) ; R11.2@32.463,8.45 32.463,7.927 32.714,7.676 35.2,7.676 36.6,9.076 v1(36.6,9.91)
  BOTTOM w0.15: J3.4 18.04,2.6 20,2.6 20.4,3 22.3,3 22.7,3.4 24.851,3.4 25.854,4.403 30.267,4.403 34.733,8.87 NRST.X 35.722,8.87 35.722,9.062 36.57,9.91 v1(36.6,9.91) 36.514,9.996 36.514,10.197 36.488,10.223 36.488,11.897 36.769,12.178 37.871,12.178 38.165,12.472 38.165,12.888 37.805,13.248 36.992,13.248 36.798,13.442 36.798,14.194 35.954,15.038 34.356,15.038 32.318,17.076 32.318,17.88 31.252,18.946 31.252,20.778 v1(30.63,21.4)
SCL_1: J1.4 J2.4 J4.4 R3.1 SCL.X U1.18 | length 55.5
  TOP w0.15: v1(3.886,10.486) 3.886,10.916 4.15,11.18 J1.4 ; v1(3.9,12.9) 3.9,14.573 5.011,15.684 7,15.684 ; R3.1 7.039,15.644 7,15.684 ; v1(14.9,21.3) 14.914,21.286 14.914,20.614 13.2,18.9 10.487,18.9 7.271,15.684 7,15.684 ; v1(20.9,22.8) 22.581,22.8 23.891,24.11 J4.4 24.355,24.155 26.855,24.155 v1(26.9,24.2) 27.21,24.51 30.151,24.51 30.8,23.861 U1.18 ; v1(34.1,13.8) 34.48,14.18 J2.4
  BOTTOM w0.15: SCL.X 3.5,12.5 v1(3.9,12.9) ; SCL.X@3.694,11.557 3.694,11.14 3.886,10.948 v1(3.886,10.486) ; v1(14.9,21.3) 19.4,21.3 v1(20.9,22.8) ; v1(26.9,24.2) 27.233,23.867 27.233,22.584 27.722,22.095 28.383,22.095 30.625,19.853 30.625,16.616 31.072,16.169 31.964,16.169 33.793,14.34 33.793,14.107 v1(34.1,13.8)
SDA_1: J1.3 J2.3 J4.3 R2.1 SDA.X U1.19 | length 58
  TOP w0.15: R2.1 6.477,10.805 6.389,10.893 6.389,11.87 6.079,12.18 3.598,12.18 3.186,12.592 3,12.778 v1(3,12.9) 3.448,13.348 3.448,14.709 4.94,16.2 6.949,16.2 10.049,19.3 12.8,19.3 v1(14.2,20.7) ; v1(23.4,22.8) 23.438,22.762 24.69,22.762 25.527,23.599 v1(26.477,23.599) 26.499,23.577 27.077,23.577 27.56,24.06 29.988,24.06 30.3,23.748 U1.19 ; v1(34.1,13.073) 34.744,13.073 34.851,13.18 J2.3 J2.3@35.696,13.21
  BOTTOM w0.15: v1(3,12.9) 3,13.45 SDA.X ; v1(14.2,20.7) 19.85,20.7 21.926,22.776 ; J4.3 21.926,23.954 21.926,22.776 ; v1(23.4,22.8) 23.376,22.776 21.926,22.776 ; v1(26.477,23.599) 26.477,22.948 27.608,21.818 28.268,21.818 30.348,19.738 30.348,16.501 30.958,15.892 31.849,15.892 33.516,14.225 33.516,13.657 v1(34.1,13.073)
pads on no net: Fiducial_1.1 Fiducial_2.1 Fiducial_3.1 PA6.X PA7.X PC14.X PC15.X TP9.X TP10.X TP11.X TP12.X

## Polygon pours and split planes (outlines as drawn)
+3V3 on TOP "NONET_L04_P-001" (solid, remove dead copper, pour order 6): 0,4.5 ccw(c4.5,4.5) 4.5,0 36.5,0 ccw(c36.5,4.5) 41,4.5 41,20.86 ccw(c36.5,20.86) 36.5,25.36 4.5,25.36 ccw(c4.5,20.86) 0,20.86
GND on TOP "NONET_L04_P-001" (solid, remove dead copper, pour order 5): 41,25.36 41,0 37.8,0 37.8,25.36
GND on TOP "NONET_L04_P-001" (solid, remove dead copper, pour order 4): 0,25.36 0,0 3.2,0 3.2,25.36
GND on BOTTOM "NONET_L04_P-001" (solid, remove dead copper, pour order 9): 0,4.5 ccw(c4.5,4.5) 4.5,0 36.5,0 ccw(c36.5,4.5) 41,4.5 41,20.86 ccw(c36.5,20.86) 36.5,25.36 4.5,25.36 ccw(c4.5,20.86) 0,20.86
+3V3 on BOTTOM "+3V3_L02_P008" (solid, remove dead copper, pour order 8): 34.7,11.7 34.7,12.743 31.743,15.7 30.9,15.7 29.7,16.9 29.7,17.8 27.5,17.8 27.5,16.46 28.8,15.16 28.8,13.384 31.646,13.384 32.05,12.979 32.05,12.25 32.6,11.7
+3V3 on BOTTOM "+3V3_L02_P007" (solid, remove dead copper, pour order 7): 6.829,12.68 6.829,13.129 7.626,13.926 11.2,13.926 11.2,17.5 9.6,17.5 5.82,13.72 5.82,12.68

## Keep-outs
Keep-Out Layer:
  circle w0.05: c36.5,4.68 r2.75
  circle w0.05: c36.5,20.68 r2.75
  circle w0.05: c4.5,4.68 r2.75
  circle w0.05: c4.5,20.68 r2.75

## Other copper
BOTTOM:
  region: 589 vertices and 0 holes, not listed, extent 36.947,15.938 38.059,17.027

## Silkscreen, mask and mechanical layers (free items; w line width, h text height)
Route Tool Path:
  lines w2: -1,8.498 -1,16.86 ; 42,4.5 cw(c36.5,4.5) 36.5,-1 ; 42,8.498 42,16.86 ; -1,4.498 ccw(c4.5,4.5) 4.498,-1 ; -1,4.498 cw(c4.5,4.5) -1,4.5 ccw(c0,4.5) -1,4.498 ; -1,20.86 cw(c4.5,20.86) 4.5,26.36 ; -1,20.86 -1,20.86 ; 4.498,-1 ccw(c4.5,4.5) 4.5,-1 ; 4.498,-1 ccw(c4.5,0) 4.5,-1 ; 4.5,-1 36.5,-1 ; 4.5,26.36 36.5,26.36 ; 4.5,26.36 4.5,26.36 ; 36.5,-1 36.5,-1 ; 36.5,26.36 cw(c36.5,20.86) 36.502,26.36 ; 36.5,26.36 cw(c36.5,25.36) 36.502,26.36 ; 36.502,26.36 cw(c36.5,20.86) 42,20.863 ; 42,20.863 cw(c41,20.86) 42,20.86 ccw(c36.5,20.86) 42,20.863
Board:
  the board outline again, w0.05
Mechanical 33:
  lines w0.05: 8.44,1.25 9.07,1.25 ; 9.07,0.62 9.07,1.25 ; 9.07,1.88 9.07,1.25 ; 9.7,1.25 9.07,1.25 ; 10.98,1.25 11.61,1.25 ; 11.61,0.62 11.61,1.25 ; 11.61,1.88 11.61,1.25 ; 12.24,1.25 11.61,1.25 ; 13.52,1.25 14.15,1.25 ; 14.15,0.62 14.15,1.25 ; 14.15,1.88 14.15,1.25 ; 14.78,1.25 14.15,1.25 ; 16.06,1.25 16.69,1.25 ; 16.06,24.11 16.69,24.11 ; 16.69,0.62 16.69,1.25 ; 16.69,1.88 16.69,1.25 ; 16.69,23.48 16.69,24.11 ; 16.69,24.74 16.69,24.11 ; 17.32,1.25 16.69,1.25 ; 17.32,24.11 16.69,24.11 ; 18.6,1.25 19.23,1.25 ; 18.6,24.11 19.23,24.11 ; 19.23,0.62 19.23,1.25 ; 19.23,1.88 19.23,1.25 ; 19.23,23.48 19.23,24.11 ; 19.23,24.74 19.23,24.11 ; 19.86,1.25 19.23,1.25 ; 19.86,24.11 19.23,24.11 ; 21.14,1.25 21.77,1.25 ; 21.14,24.11 21.77,24.11 ; 21.77,0.62 21.77,1.25 ; 21.77,1.88 21.77,1.25 ; 21.77,23.48 21.77,24.11 ; 21.77,24.74 21.77,24.11 ; 22.4,1.25 21.77,1.25 ; 22.4,24.11 21.77,24.11 ; 23.68,1.25 24.31,1.25 ; 23.68,24.11 24.31,24.11 ; 24.31,0.62 24.31,1.25 ; 24.31,1.88 24.31,1.25 ; 24.31,23.48 24.31,24.11 ; 24.31,24.74 24.31,24.11 ; 24.94,1.25 24.31,1.25 ; 24.94,24.11 24.31,24.11 ; 26.22,1.25 26.85,1.25 ; 26.85,0.62 26.85,1.25 ; 26.85,1.88 26.85,1.25 ; 27.48,1.25 26.85,1.25 ; 28.76,1.25 29.39,1.25 ; 29.39,0.62 29.39,1.25 ; 29.39,1.88 29.39,1.25 ; 30.02,1.25 29.39,1.25 ; 31.3,1.25 31.93,1.25 ; 31.93,0.62 31.93,1.25 ; 31.93,1.88 31.93,1.25 ; 32.56,1.25 31.93,1.25
Mechanical 66:
  circle w0.05: c36.5,4.68 r2.85
  circle w0.05: c36.5,20.68 r2.85
  circle w0.05: c4.5,20.68 r2.85
  circle w0.05: c4.5,4.68 r2.85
